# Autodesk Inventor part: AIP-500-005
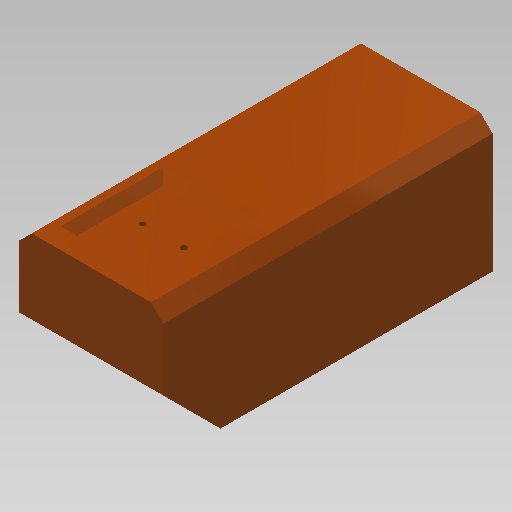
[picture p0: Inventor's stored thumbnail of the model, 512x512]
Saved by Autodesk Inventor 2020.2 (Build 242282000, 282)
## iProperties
Created: 2014-06
Part Number: AIP-500-005
Material: Ogólny
Document SubType Name: Modeling
Designer: F.Stasiak
Density: 1 g/cm^3
Appearance: Gładki - jasnopomarańczowy
Catalog Web Link: www.expertbooks.pl
Manager: www.cadconsulting.pl
Company: Fabian Stasiak CAD Consulting
Author: F.Stasiak
Subject: Zbiór ćwiczeń. Autodesk Inventor 2020. Kurs Professional
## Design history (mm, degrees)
sketch "Szkic1"
  geometry: L1 (175, -175)-(-175, -175); L2 (-175, -175)-(-175, 175); L3 (-175, 175)-(175, 175); L4 (175, 175)-(175, -175); L5 (175, -175)-(-175, 175); L6 (-175, -175)-(175, 175); 1 further point
  constraints: 12 end point, 2 midpoint, 2 parallel, 1 horizontal, 1 perpendicular
  dimensions: "d0" = 350 distance of L2.end L3.end; "d1" = 350 distance of L1.end L2.end
extrude "Wyciągnięcie proste1" new body sketch "Szkic1" distance "d2" = 800; taper "d3" = 0 deg
sketch "Szkic2"
  geometry: L1 (0, 0)-(0, -800) reference; L2 (350, -800)-(0, -800) reference; L3 (350, 0)-(350, -800) reference; L4 (300, -750)-(50, -750); L5 (50, -750)-(50, -500); L6 (50, -500)-(300, -500); L7 (300, -500)-(300, -750); 1 further point
  constraints: 8 end point, 2 parallel, 2 perpendicular, 1 horizontal
  dimensions: "d4" = 50 distance between parallel lines of L7 L3; "d5" = 50 distance between parallel lines of L1 L5 (= d4); "d6" = 50 distance between parallel lines of L2 L4 (= d4)
extrude "Wyciągnięcie proste2" cut sketch "Szkic2" distance "d7" = 20; taper "d8" = -45 deg
chamfer "Faza1" distance "d9" = 30; stored, may be unused: second distance "d10" = 2, angle "d11" = 45 deg
chamfer "Faza2" distance "d12" = 168.75; stored, may be unused: second distance "d13" = 2, angle "d14" = 45 deg
sketch "Szkic3"
  geometry: L1 (280, -730)-(280, -520) reference; L2 (70, -730)-(280, -730) reference; L3 (225, -625)-(125, -625); 4 further points
  constraints: 3 midpoint, 2 end point, 1 parallel, 1 point on line, 1 vertical alignment
  dimensions: "d15" = 100 distance of L3.start L3.end
hole "Otwór1" sketch "Szkic3" at (225, -625), (125, -625) diameter "d16" = 15; stored, may be unused: countersink angle "d20" = 90 deg, drill point angle "d22" = 118 deg; dims "d17" = 6, "d18" = 4, "d19" = 2, "d21" = 15
node "Bryła1"
